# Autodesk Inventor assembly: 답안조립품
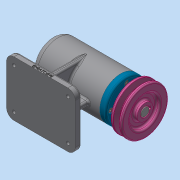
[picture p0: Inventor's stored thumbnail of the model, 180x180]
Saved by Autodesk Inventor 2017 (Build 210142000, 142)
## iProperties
Part Number: 답안조립품
Material: 일반
Document SubType Name: Assembly
Designer: mrc
Author: mrc
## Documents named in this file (12)
- C:\Users\mrc\Desktop\701004V1029\답안조립품.iam
- C:\Users\mrc\Desktop\701004V1029\본체.ipt
- C:\Users\mrc\Desktop\701004V1029\V벨트풀리.ipt
- C:\Users\mrc\Desktop\701004V1029\멈춤나사 M3.ipt
- C:\Users\mrc\Desktop\701004V1029\베어링 6004.ipt
- C:\Users\mrc\Desktop\701004V1029\베어링 51202.ipt
- C:\Users\mrc\Desktop\701004V1029\볼트 M4.ipt
- C:\Users\mrc\Desktop\701004V1029\어댑터슬리브.ipt
- C:\Users\mrc\Desktop\701004V1029\오일 실.ipt
- C:\Users\mrc\Desktop\701004V1029\축.ipt
- C:\Users\mrc\Desktop\701004V1029\커버.ipt
- C:\Users\mrc\Desktop\701004V1029\키 5 x 5 x 16.ipt
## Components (1 placed, 1 different names)
1. V벨트풀리:1
